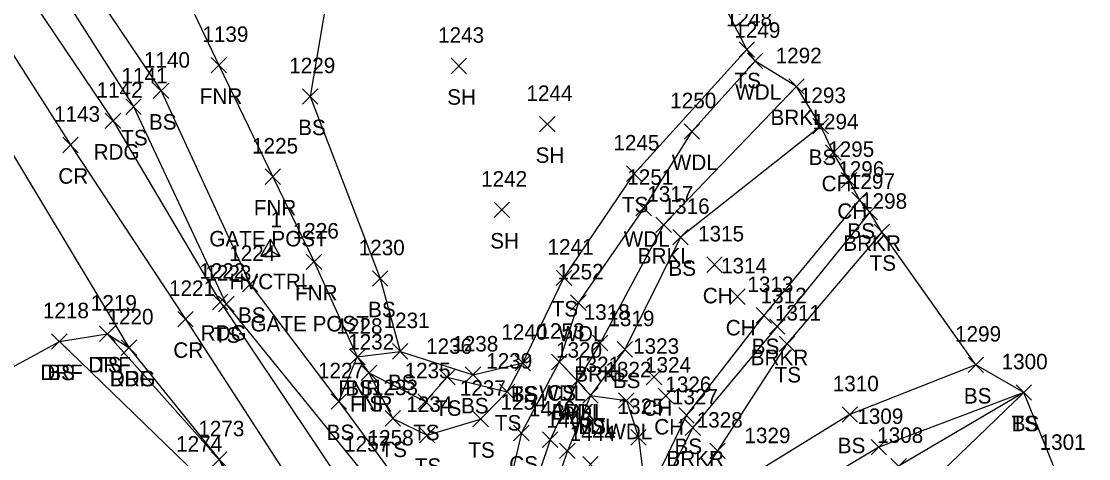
# Model space of a CAD drawing. Extents: x 1441651 to 1442140, y 243798 to 245625.
# Drawn here: x 1441999.2 to 1442137.1, y 245444.6 to 245501.1 of the extents above; entities that cross this region are included whole.
import ezdxf

# ---------------------------------------------------------------- set-up
doc = ezdxf.new("R2010")
doc.units = 0
for name, color, linetype in [('C_A', 7, 'Continuous'), ('C_I', 7, 'Continuous'), ('CPSM', 7, 'Continuous'), ('L_A', 7, 'Continuous'), ('L_C', 7, 'Continuous'), ('L_I', 7, 'Continuous'), ('L_TIC', 7, 'Continuous'), ('LAWA', 7, 'Continuous'), ('LAWE', 7, 'Continuous'), ('LELB', 7, 'Continuous'), ('LFNC', 7, 'Continuous'), ('LSOGP', 7, 'Continuous'), ('P_A', 7, 'Continuous'), ('P_I', 7, 'Continuous'), ('P_TIC', 7, 'Continuous'), ('PEU', 7, 'Continuous'), ('PRC', 7, 'Continuous'), ('R_A', 7, 'Continuous'), ('R_I', 7, 'Continuous'), ('R_TIC', 7, 'Continuous'), ('RDF', 7, 'Continuous')]:
    doc.layers.add(name, color=color, linetype=linetype)

msp = doc.modelspace()

# ---------------------------------------------------------------- linework, layer by layer
at = {"layer": 'CPSM'}
for p, q in [((1442030.12, 245470.79), (1442031.37, 245472.96)), ((1442032.62, 245470.79), (1442031.37, 245472.96)), ((1442031.37, 245471.51), (1442031.37, 245472.96)), ((1442030.12, 245470.79), (1442031.37, 245471.51)), ((1442031.37, 245471.51), (1442031.37, 245471.51)), ((1442031.37, 245471.51), (1442032.62, 245470.79)), ((1442030.12, 245470.79), (1442032.62, 245470.79))]:
    msp.add_line(p, q, dxfattribs=at)
at = {"layer": 'L_TIC'}
for points in [[(1442091.91, 245496.47), (1442093.91, 245498.47)], [(1442093.91, 245496.47), (1442091.91, 245498.47)], [(1442023.69, 245494.45), (1442025.69, 245496.45)], [(1442025.69, 245494.45), (1442023.69, 245496.45)], [(1442054.71, 245494.34), (1442056.71, 245496.34)], [(1442056.71, 245494.34), (1442054.71, 245496.34)], [(1442093, 245494.98), (1442095, 245496.98)], [(1442095, 245494.98), (1442093, 245496.98)], [(1442016.22, 245491.13), (1442018.22, 245493.13)], [(1442018.22, 245491.13), (1442016.22, 245493.13)], [(1442098.33, 245491.7), (1442100.33, 245493.7)], [(1442100.33, 245491.7), (1442098.33, 245493.7)], [(1442035.49, 245490.41), (1442037.49, 245492.41)], [(1442037.49, 245490.41), (1442035.49, 245492.41)], [(1442035.49, 245490.41), (1442037.49, 245492.41)], [(1442037.49, 245490.41), (1442035.49, 245492.41)], [(1442012.67, 245489.09), (1442014.67, 245491.09)], [(1442014.67, 245489.09), (1442012.67, 245491.09)], [(1442066.14, 245486.83), (1442068.14, 245488.83)], [(1442068.14, 245486.83), (1442066.14, 245488.83)], [(1442084.8, 245485.89), (1442086.8, 245487.89)], [(1442086.8, 245485.89), (1442084.8, 245487.89)], [(1442101.46, 245486.56), (1442103.46, 245488.56)], [(1442103.46, 245486.56), (1442101.46, 245488.56)], [(1442103.09, 245483.16), (1442105.09, 245485.16)], [(1442105.09, 245483.16), (1442103.09, 245485.16)], [(1442030.67, 245480.04), (1442032.67, 245482.04)], [(1442032.67, 245480.04), (1442030.67, 245482.04)], [(1442077.37, 245480.43), (1442079.37, 245482.43)], [(1442079.37, 245480.43), (1442077.37, 245482.43)], [(1442105.12, 245479.6), (1442107.12, 245481.6)], [(1442107.12, 245479.6), (1442105.12, 245481.6)], [(1442060.27, 245475.77), (1442062.27, 245477.77)], [(1442062.27, 245475.77), (1442060.27, 245477.77)], [(1442078.59, 245476), (1442080.59, 245478)], [(1442080.59, 245476), (1442078.59, 245478)], [(1442106.48, 245477.04), (1442108.48, 245479.04)], [(1442108.48, 245477.04), (1442106.48, 245479.04)], [(1442107.8, 245475.47), (1442109.8, 245477.47)], [(1442109.8, 245475.47), (1442107.8, 245477.47)], [(1442081.17, 245473.83), (1442083.17, 245475.83)], [(1442083.17, 245473.83), (1442081.17, 245475.83)], [(1442083.35, 245472.24), (1442085.35, 245474.24)], [(1442085.35, 245472.24), (1442083.35, 245474.24)], [(1442109.37, 245472.9), (1442111.37, 245474.9)], [(1442111.37, 245472.9), (1442109.37, 245474.9)], [(1442035.99, 245469.06), (1442037.99, 245471.06)], [(1442037.99, 245469.06), (1442035.99, 245471.06)], [(1442087.73, 245468.69), (1442089.73, 245470.69)], [(1442089.73, 245468.69), (1442087.73, 245470.69)], [(1442027.73, 245466.17), (1442029.73, 245468.17)], [(1442029.73, 245466.17), (1442027.73, 245468.17)], [(1442044.54, 245466.9), (1442046.54, 245468.9)], [(1442046.54, 245466.9), (1442044.54, 245468.9)], [(1442068.29, 245466.99), (1442070.29, 245468.99)], [(1442070.29, 245466.99), (1442068.29, 245468.99)], [(1442024.65, 245463.6), (1442026.65, 245465.6)], [(1442026.65, 245463.6), (1442024.65, 245465.6)], [(1442070.15, 245463.78), (1442072.15, 245465.78)], [(1442072.15, 245463.78), (1442070.15, 245465.78)], [(1442090.7, 245464.55), (1442092.7, 245466.55)], [(1442092.7, 245464.55), (1442090.7, 245466.55)], [(1442094.11, 245462.14), (1442096.11, 245464.14)], [(1442096.11, 245462.14), (1442094.11, 245464.14)], [(1442095.83, 245460.7), (1442097.83, 245462.7)], [(1442097.83, 245460.7), (1442095.83, 245462.7)], [(1442009.28, 245459.76), (1442011.28, 245461.76)], [(1442011.28, 245459.76), (1442009.28, 245461.76)], [(1442003.08, 245458.77), (1442005.08, 245460.77)], [(1442005.08, 245458.77), (1442003.08, 245460.77)], [(1442072.96, 245458.56), (1442074.96, 245460.56)], [(1442074.96, 245458.56), (1442072.96, 245460.56)], [(1442097.1, 245458.47), (1442099.1, 245460.47)], [(1442099.1, 245458.47), (1442097.1, 245460.47)], [(1442041.58, 245456.76), (1442043.58, 245458.76)], [(1442043.58, 245456.76), (1442041.58, 245458.76)], [(1442041.58, 245456.76), (1442043.58, 245458.76)], [(1442043.58, 245456.76), (1442041.58, 245458.76)], [(1442047.11, 245457.49), (1442049.11, 245459.49)], [(1442049.11, 245457.49), (1442047.11, 245459.49)], [(1442047.11, 245457.49), (1442049.11, 245459.49)], [(1442049.11, 245457.49), (1442047.11, 245459.49)], [(1442076.16, 245457.74), (1442078.16, 245459.74)], [(1442078.16, 245457.74), (1442076.16, 245459.74)], [(1442062.98, 245455.99), (1442064.98, 245457.99)], [(1442064.98, 245455.99), (1442062.98, 245457.99)], [(1442062.98, 245455.99), (1442064.98, 245457.99)], [(1442064.98, 245455.99), (1442062.98, 245457.99)], [(1442067.68, 245456.12), (1442069.68, 245458.12)], [(1442069.68, 245456.12), (1442067.68, 245458.12)], [(1442067.68, 245456.12), (1442069.68, 245458.12)], [(1442069.68, 245456.12), (1442067.68, 245458.12)], [(1442121.52, 245455.75), (1442123.52, 245457.75)], [(1442123.52, 245455.75), (1442121.52, 245457.75)], [(1442043.09, 245454.72), (1442045.09, 245456.72)], [(1442045.09, 245454.72), (1442043.09, 245456.72)], [(1442043.09, 245454.72), (1442045.09, 245456.72)], [(1442045.09, 245454.72), (1442043.09, 245456.72)], [(1442043.09, 245454.72), (1442045.09, 245456.72)], [(1442045.09, 245454.72), (1442043.09, 245456.72)], [(1442053.21, 245454.16), (1442055.21, 245456.16)], [(1442055.21, 245454.16), (1442053.21, 245456.16)], [(1442056.54, 245454.47), (1442058.54, 245456.47)], [(1442058.54, 245454.47), (1442056.54, 245456.47)], [(1442079.92, 245454.17), (1442081.92, 245456.17)], [(1442081.92, 245454.17), (1442079.92, 245456.17)], [(1442070.04, 245453.67), (1442072.04, 245455.67)], [(1442072.04, 245453.67), (1442070.04, 245455.67)], [(1442070.04, 245453.67), (1442072.04, 245455.67)], [(1442072.04, 245453.67), (1442070.04, 245455.67)], [(1442039.19, 245451.02), (1442041.19, 245453.02)], [(1442041.19, 245451.02), (1442039.19, 245453.02)], [(1442039.19, 245451.02), (1442041.19, 245453.02)], [(1442041.19, 245451.02), (1442039.19, 245453.02)], [(1442050.39, 245451.01), (1442052.39, 245453.01)], [(1442052.39, 245451.01), (1442050.39, 245453.01)], [(1442060.95, 245452.26), (1442062.95, 245454.26)], [(1442062.95, 245452.26), (1442060.95, 245454.26)], [(1442060.95, 245452.26), (1442062.95, 245454.26)], [(1442062.95, 245452.26), (1442060.95, 245454.26)], [(1442071.72, 245451.8), (1442073.72, 245453.8)], [(1442073.72, 245451.8), (1442071.72, 245453.8)], [(1442071.72, 245451.8), (1442073.72, 245453.8)], [(1442073.72, 245451.8), (1442071.72, 245453.8)], [(1442076.35, 245451.14), (1442078.35, 245453.14)], [(1442078.35, 245451.14), (1442076.35, 245453.14)], [(1442081.46, 245451.75), (1442083.46, 245453.75)], [(1442083.46, 245451.75), (1442081.46, 245453.75)], [(1442127.7, 245452.17), (1442129.7, 245454.17)], [(1442129.7, 245452.17), (1442127.7, 245454.17)], [(1442127.7, 245452.17), (1442129.7, 245454.17)], [(1442129.7, 245452.17), (1442127.7, 245454.17)], [(1442127.7, 245452.17), (1442129.7, 245454.17)], [(1442129.7, 245452.17), (1442127.7, 245454.17)], [(1442046.17, 245448.83), (1442048.17, 245450.83)], [(1442048.17, 245448.83), (1442046.17, 245450.83)], [(1442057.52, 245448.75), (1442059.52, 245450.75)], [(1442059.52, 245448.75), (1442057.52, 245450.75)], [(1442084.12, 245449.23), (1442086.12, 245451.23)], [(1442086.12, 245449.23), (1442084.12, 245451.23)], [(1442105.23, 245449.33), (1442107.23, 245451.33)], [(1442107.23, 245449.33), (1442105.23, 245451.33)], [(1442062.78, 245446.95), (1442064.78, 245448.95)], [(1442064.78, 245446.95), (1442062.78, 245448.95)], [(1442084.94, 245447.64), (1442086.94, 245449.64)], [(1442086.94, 245447.64), (1442084.94, 245449.64)], [(1442050.6, 245446.67), (1442052.6, 245448.67)], [(1442052.6, 245446.67), (1442050.6, 245448.67)], [(1442066.5, 245446.08), (1442068.5, 245448.08)], [(1442068.5, 245446.08), (1442066.5, 245448.08)], [(1442077.91, 245446.39), (1442079.91, 245448.39)], [(1442079.91, 245446.39), (1442077.91, 245448.39)], [(1442068.73, 245444.65), (1442070.73, 245446.65)], [(1442070.73, 245444.65), (1442068.73, 245446.65)], [(1442088.13, 245444.64), (1442090.13, 245446.64)], [(1442090.13, 245444.64), (1442088.13, 245446.64)], [(1442108.97, 245445.11), (1442110.97, 245447.11)], [(1442110.97, 245445.11), (1442108.97, 245447.11)], [(1442023.73, 245443.52), (1442025.73, 245445.52)], [(1442025.73, 245443.52), (1442023.73, 245445.52)], [(1442071.71, 245442.9), (1442073.71, 245444.9)], [(1442073.71, 245442.9), (1442071.71, 245444.9)], [(1442111.53, 245442.67), (1442113.53, 245444.67)], [(1442113.53, 245442.67), (1442111.53, 245444.67)]]:
    msp.add_lwpolyline(points, dxfattribs=at)
at = {"layer": 'LAWA'}
msp.add_lwpolyline([(1442094, 245495.98), (1442085.8, 245486.89), (1442079.59, 245477), (1442071.15, 245464.78), (1442068.68, 245457.12), (1442071.04, 245454.67), (1442072.72, 245452.8), (1442077.35, 245452.14), (1442078.91, 245447.39), (1442079.93, 245439.38), (1442079.45, 245435.79), (1442079.26, 245431.04), (1442079.31, 245426.05), (1442080.91, 245421.58), (1442082.68, 245419.01), (1442083.61, 245417.34), (1442086, 245415.06), (1442087.36, 245410.97), (1442093.76, 245403.64), (1442092.69, 245393.5), (1442088.17, 245379.01), (1442081.06, 245357.62), (1442070.18, 245342.03)], dxfattribs=at)
at = {"layer": 'LAWE'}
for points in [[(1442099.33, 245492.7), (1442082.17, 245474.83), (1442073.96, 245459.56), (1442071.04, 245454.67), (1442067.5, 245447.08), (1442064.77, 245439.02), (1442060.82, 245433.99), (1442057.71, 245424.57), (1442056.02, 245422.42), (1442050.95, 245416.77), (1442046.42, 245406.15), (1442038.47, 245397.39), (1442033, 245390.02), (1442022.03, 245379.96), (1442015.44, 245373.01), (1442011.82, 245364.95), (1441999.31, 245341.93), (1441993.28, 245326.59), (1441983.7, 245301.8)], [(1442108.8, 245476.47), (1442096.83, 245461.7), (1442085.94, 245448.64), (1442079.45, 245435.79), (1442078.13, 245432.44), (1442074.22, 245419.93), (1442069.91, 245412.33), (1442066.17, 245406.44), (1442060.08, 245400.81), (1442053.87, 245394.97), (1442048.8, 245389.02), (1442033.75, 245369.5), (1442027.29, 245353.92), (1442016.14, 245332.93), (1442008.36, 245317.18), (1442000.26, 245295.5)]]:
    msp.add_lwpolyline(points, dxfattribs=at)
at = {"layer": 'LELB'}
for points in [[(1441958.14, 245603.85), (1441973.05, 245572.7), (1441987.15, 245544.68), (1442001.28, 245515.81), (1442017.22, 245492.13), (1442028.73, 245467.17), (1442040.19, 245452.02), (1442046.6, 245443.33), (1442055.54, 245439.06), (1442059.34, 245437.76)], [(1441952, 245600.36), (1441967.38, 245569.64), (1441982.75, 245542), (1441998.18, 245514.4), (1442013.67, 245490.09), (1442025.65, 245464.6), (1442043.56, 245442.55), (1442056.06, 245427.98)], [(1442054.94, 245535.31), (1442039.85, 245511.24), (1442036.49, 245491.41)], [(1442044.09, 245455.72), (1442051.39, 245452.01), (1442054.21, 245455.16), (1442061.95, 245453.26), (1442063.98, 245456.99), (1442069.29, 245467.99), (1442078.37, 245481.43), (1442092.91, 245497.47)], [(1442036.49, 245491.41), (1442045.54, 245467.9), (1442048.11, 245458.49), (1442057.54, 245455.47), (1442063.98, 245456.99)], [(1442102.46, 245487.56), (1442084.35, 245473.24), (1442077.16, 245458.74), (1442072.72, 245452.8), (1442069.73, 245445.65), (1442066.87, 245437.14), (1442063.41, 245431.6), (1442060.35, 245422.41), (1442058.71, 245418.73), (1442054.41, 245414.05), (1442047.26, 245402.98), (1442041.76, 245394.88), (1442035.1, 245387.22), (1442025.14, 245377.83), (1442014.24, 245362.92), (1442001.68, 245340.27), (1441995.17, 245325.26), (1441985.52, 245301.17)], [(1442107.48, 245478.04), (1442095.11, 245463.14), (1442085.12, 245450.23), (1442079.93, 245439.38), (1442074.02, 245430.6), (1442072.19, 245422.42), (1442067.6, 245415.77), (1442063.53, 245410.87), (1442058.94, 245403.45), (1442051.47, 245396.66), (1442047.36, 245390.55), (1442031.62, 245371.64), (1442024.89, 245355.94), (1442013.33, 245334.79), (1442005.48, 245318.66), (1441997.83, 245296.61)], [(1442110.37, 245473.9), (1442098.1, 245459.47), (1442089.13, 245445.64), (1442079.26, 245431.04)], [(1442010.28, 245460.76), (1442024.73, 245444.52), (1442033.88, 245425.53)], [(1442004.08, 245459.77), (1442021.87, 245442.55), (1442025.23, 245431.01), (1442028.78, 245424.28), (1442039.93, 245412.91)], [(1442040.19, 245452.02), (1442042.58, 245457.76), (1442048.11, 245458.49)], [(1442068.68, 245457.12), (1442063.78, 245447.95), (1442061.76, 245439.31), (1442059.81, 245436.82), (1442059.01, 245434.53), (1442059.88, 245434.24)], [(1442044.09, 245455.72), (1442047.17, 245449.83), (1442051.6, 245447.67), (1442058.52, 245449.75), (1442061.95, 245453.26)], [(1442122.52, 245456.75), (1442106.23, 245450.33), (1442095.31, 245443.63), (1442083.42, 245430.81), (1442079.31, 245426.05)], [(1442128.7, 245453.17), (1442114.47, 245439.46), (1442106.29, 245436.04), (1442091.13, 245416.25), (1442087.36, 245410.97), (1442078.92, 245407.7), (1442072.37, 245401.79), (1442078.66, 245393.32), (1442088.17, 245379.01), (1442078.35, 245359.72), (1442066.47, 245343.93), (1442051.62, 245313.9)], [(1442128.7, 245453.17), (1442112.53, 245443.67), (1442104.21, 245438.02), (1442088.68, 245419.94), (1442086, 245415.06), (1442079.92, 245412.18)], [(1442128.7, 245453.17), (1442109.97, 245446.11), (1442099.05, 245439.57), (1442087, 245426.32)]]:
    msp.add_lwpolyline(points, dxfattribs=at)
at = {"layer": 'LFNC'}
msp.add_lwpolyline([(1441970.22, 245607.54), (1441978.86, 245588.2), (1441995.27, 245556.04), (1442014.76, 245516.33), (1442024.69, 245495.45), (1442031.67, 245481.04), (1442036.99, 245470.06), (1442042.58, 245457.76), (1442044.09, 245455.72)], dxfattribs=at)
at = {"layer": 'LSOGP'}
msp.add_lwpolyline([(1442101.45, 245340.82), (1442116.12, 245368.4), (1442121.58, 245390.94), (1442129.6, 245411.58), (1442137.09, 245433.29), (1442136.43, 245438.34), (1442132.95, 245442.77), (1442128.7, 245453.17), (1442122.52, 245456.75), (1442110.37, 245473.9), (1442108.8, 245476.47), (1442107.48, 245478.04), (1442106.12, 245480.6), (1442104.09, 245484.16), (1442102.46, 245487.56), (1442099.33, 245492.7), (1442094, 245495.98), (1442092.91, 245497.47), (1442087.1, 245508.94)], dxfattribs=at)
at = {"layer": 'P_TIC'}
for points in [[(1442010.02, 245487.25), (1442012.02, 245489.25)], [(1442012.02, 245487.25), (1442010.02, 245489.25)], [(1442004.51, 245484.14), (1442006.51, 245486.14)], [(1442006.51, 245484.14), (1442004.51, 245486.14)], [(1442023.85, 245463.87), (1442025.85, 245465.87)], [(1442025.85, 245463.87), (1442023.85, 245465.87)], [(1442019.38, 245461.65), (1442021.38, 245463.65)], [(1442021.38, 245461.65), (1442019.38, 245463.65)], [(1442012.08, 245457.97), (1442014.08, 245459.97)], [(1442014.08, 245457.97), (1442012.08, 245459.97)], [(1442023.73, 245443.52), (1442025.73, 245445.52)], [(1442025.73, 245443.52), (1442023.73, 245445.52)]]:
    msp.add_lwpolyline(points, dxfattribs=at)
at = {"layer": 'PEU'}
for points in [[(1441949.7, 245598.81), (1441965.58, 245568.64), (1441979.81, 245540.54), (1441994.5, 245512.77), (1442011.02, 245488.25), (1442024.85, 245464.87), (1442045.34, 245434.3), (1442053.64, 245424.38)], [(1441937.94, 245591.88), (1441953.89, 245562.72), (1441968.91, 245535.69), (1441984.8, 245506.98), (1441992.99, 245492.3), (1442013.08, 245458.97), (1442024.73, 245444.52), (1442043.13, 245414.63), (1442048.27, 245419.3), (1442053.64, 245424.38)]]:
    msp.add_lwpolyline(points, dxfattribs=at)
at = {"layer": 'PRC'}
msp.add_lwpolyline([(1441943.37, 245595.22), (1441959.06, 245565.31), (1441973.71, 245538.05), (1441989.92, 245509.63), (1442005.51, 245485.14), (1442020.38, 245462.65), (1442040.92, 245430.94), (1442048.27, 245419.3)], dxfattribs=at)
at = {"layer": 'R_TIC'}
for points in [[(1442009.28, 245459.76), (1442011.28, 245461.76)], [(1442011.28, 245459.76), (1442009.28, 245461.76)], [(1442003.08, 245458.77), (1442005.08, 245460.77)], [(1442005.08, 245458.77), (1442003.08, 245460.77)], [(1442012.08, 245457.97), (1442014.08, 245459.97)], [(1442014.08, 245457.97), (1442012.08, 245459.97)]]:
    msp.add_lwpolyline(points, dxfattribs=at)
at = {"layer": 'RDF'}
msp.add_lwpolyline([(1441992.99, 245492.3), (1441993.22, 245488.68), (1441992.69, 245484.34), (1441989.24, 245472.33), (1441979.84, 245465.31), (1441969.62, 245458.62), (1441982.23, 245444.74), (1441988.43, 245451.23), (1442004.08, 245459.77), (1442010.28, 245460.76), (1442013.08, 245458.97)], dxfattribs=at)

# ---------------------------------------------------------------- texts
at = {"layer": 'C_A'}
msp.add_text('HVCTRL', height=2, dxfattribs=at).set_placement((1442026.07, 245466.51))
at = {"layer": 'C_I'}
msp.add_text('1', height=2, dxfattribs=at).set_placement((1442031.37, 245474.51))
at = {"layer": 'L_A'}
for s, p in [('TS', (1442091.32, 245492.47)), ('WDL', (1442091.42, 245490.98)), ('FNR', (1442022.23, 245490.45)), ('SH', (1442054.2, 245490.34)), ('BS', (1442015.66, 245487.13)), ('BRKL', (1442095.98, 245487.7)), ('BS', (1442034.94, 245486.41)), ('BS', (1442034.94, 245486.41)), ('TS', (1442012.08, 245485.09)), ('SH', (1442065.62, 245482.83)), ('WDL', (1442083.22, 245481.89)), ('BS', (1442100.9, 245482.56)), ('CH', (1442102.58, 245479.16)), ('FNR', (1442029.21, 245476.04)), ('TS', (1442076.78, 245476.43)), ('CH', (1442104.61, 245475.6)), ('BS', (1442105.92, 245473.04)), ('SH', (1442059.76, 245471.77)), ('WDL', (1442077.01, 245472)), ('BRKR', (1442105.39, 245471.47)), ('BRKL', (1442078.82, 245469.83)), ('TS', (1442108.78, 245468.9)), ('BS', (1442082.79, 245468.24)), ('FNR', (1442034.53, 245465.06)), ('CH', (1442087.22, 245464.69)), ('BS', (1442027.17, 245462.17)), ('BS', (1442043.98, 245462.9)), ('TS', (1442067.7, 245462.99)), ('CH', (1442090.19, 245460.55)), ('TS', (1442024.06, 245459.6)), ('WDL', (1442068.57, 245459.78)), ('BS', (1442093.55, 245458.14)), ('BRKR', (1442093.42, 245456.7)), ('TS', (1442008.69, 245455.76)), ('BS', (1442002.52, 245454.77)), ('BRKL', (1442070.61, 245454.56)), ('BS', (1442075.6, 245453.74)), ('TS', (1442096.51, 245454.47)), ('FNR', (1442040.12, 245452.76)), ('BS', (1442041.02, 245452.76)), ('BS', (1442046.55, 245453.49)), ('BS', (1442046.55, 245453.49)), ('TS', (1442062.39, 245451.99)), ('BS', (1442062.42, 245451.99)), ('WDL', (1442066.1, 245452.12)), ('CS', (1442067.12, 245452.12)), ('BS', (1442120.96, 245451.75)), ('FNR', (1442041.63, 245450.72)), ('TS', (1442042.5, 245450.72)), ('TS', (1442042.5, 245450.72)), ('TS', (1442052.62, 245450.16)), ('BS', (1442055.98, 245450.47)), ('BRKL', (1442067.69, 245449.67)), ('WDL', (1442068.46, 245449.67)), ('CH', (1442079.41, 245450.17)), ('TS', (1442060.36, 245448.26)), ('TS', (1442060.36, 245448.26)), ('TS', (1442127.11, 245448.17)), ('TS', (1442127.11, 245448.17)), ('BS', (1442127.14, 245448.17)), ('BS', (1442038.63, 245447.02)), ('BS', (1442038.63, 245447.02)), ('TS', (1442049.8, 245447.01)), ('WDL', (1442070.13, 245447.8)), ('BS', (1442071.16, 245447.8)), ('WDL', (1442074.76, 245447.14)), ('CH', (1442080.95, 245447.75)), ('TS', (1442045.58, 245444.83)), ('TS', (1442056.93, 245444.75)), ('BS', (1442083.57, 245445.23)), ('BS', (1442104.67, 245445.33)), ('TS', (1442050.01, 245442.67)), ('CS', (1442062.22, 245442.95)), ('BRKR', (1442082.53, 245443.64))]:
    msp.add_text(s, height=2, dxfattribs=at).set_placement(p)
at = {"layer": 'L_C'}
for p in [(1442023.46, 245472.04), (1442028.78, 245461.06)]:
    msp.add_text('GATE POST', height=2, dxfattribs=at).set_placement(p)
at = {"layer": 'L_I'}
for s, p in [('1248', (1442090.22, 245500.47)), ('1139', (1442022.56, 245498.45)), ('1243', (1442053.02, 245498.34)), ('1249', (1442091.3, 245498.98)), ('1140', (1442015.01, 245495.13)), ('1292', (1442096.64, 245495.7)), ('1229', (1442033.79, 245494.41)), ('1229', (1442033.79, 245494.41)), ('1141', (1442012.11, 245493.09)), ('1244', (1442064.44, 245490.83)), ('1250', (1442083.02, 245489.89)), ('1293', (1442099.77, 245490.56)), ('1294', (1442101.4, 245487.16)), ('1225', (1442028.98, 245484.04)), ('1245', (1442075.67, 245484.43)), ('1295', (1442103.43, 245483.6)), ('1251', (1442077.47, 245480)), ('1296', (1442104.73, 245481.04)), ('1242', (1442058.58, 245479.77)), ('1297', (1442106.11, 245479.47)), ('1317', (1442080.05, 245477.83)), ('1316', (1442082.16, 245476.24)), ('1298', (1442107.68, 245476.9)), ('1226', (1442034.24, 245473.06)), ('1315', (1442086.61, 245472.69)), ('1230', (1442042.76, 245470.9)), ('1241', (1442067.16, 245470.99)), ('1224', (1442026.03, 245470.17)), ('1223', (1442022.95, 245467.6)), ('1252', (1442068.46, 245467.78)), ('1314', (1442089.58, 245468.55)), ('1313', (1442092.99, 245466.14)), ('1312', (1442094.7, 245464.7)), ('1219', (1442008.15, 245463.76)), ('1218', (1442001.96, 245462.77)), ('1318', (1442071.84, 245462.56)), ('1311', (1442096.55, 245462.47)), ('1228', (1442039.89, 245460.76)), ('1228', (1442039.89, 245460.76)), ('1231', (1442045.98, 245461.49)), ('1231', (1442045.98, 245461.49)), ('1319', (1442075.03, 245461.74)), ('1240', (1442061.2, 245459.99)), ('1240', (1442061.2, 245459.99)), ('1253', (1442065.99, 245460.12)), ('1253', (1442065.99, 245460.12)), ('1299', (1442119.82, 245459.75)), ('1232', (1442041.4, 245458.72)), ('1232', (1442041.4, 245458.72)), ('1232', (1442041.4, 245458.72)), ('1236', (1442051.47, 245458.16)), ('1238', (1442054.85, 245458.47)), ('1323', (1442078.22, 245458.17)), ('1320', (1442068.26, 245457.67)), ('1320', (1442068.26, 245457.67)), ('1239', (1442059.24, 245456.26)), ('1239', (1442059.24, 245456.26)), ('1321', (1442070.59, 245455.8)), ('1321', (1442070.59, 245455.8)), ('1322', (1442074.65, 245455.14)), ('1324', (1442079.76, 245455.75)), ('1300', (1442125.84, 245456.17)), ('1300', (1442125.84, 245456.17)), ('1300', (1442125.84, 245456.17)), ('1227', (1442037.5, 245455.02)), ('1227', (1442037.5, 245455.02)), ('1235', (1442048.69, 245455.01)), ('1233', (1442044.47, 245452.83)), ('1237', (1442055.83, 245452.75)), ('1326', (1442082.38, 245453.23)), ('1310', (1442104.02, 245453.33)), ('1254', (1442061.09, 245450.95)), ('1327', (1442083.24, 245451.64)), ('1234', (1442048.91, 245450.67)), ('1446', (1442064.75, 245450.08)), ('1325', (1442076.21, 245450.39)), ('1445', (1442067.04, 245448.65)), ('1328', (1442086.44, 245448.64)), ('1309', (1442107.19, 245449.11)), ('1273', (1442022.04, 245447.52)), ('1444', (1442070.02, 245446.9)), ('1274', (1442019.17, 245445.55)), ('1257', (1442040.87, 245445.55)), ('1258', (1442043.91, 245446.33)), ('1329', (1442092.61, 245446.63)), ('1308', (1442109.76, 245446.67)), ('1301', (1442130.75, 245445.77))]:
    msp.add_text(s, height=2, dxfattribs=at).set_placement(p)
at = {"layer": 'P_A'}
for s, p in [('RDG', (1442008.5, 245483.25)), ('CR', (1442003.95, 245480.14)), ('RDG', (1442022.34, 245459.87)), ('CR', (1442018.81, 245457.65)), ('RDG', (1442010.56, 245453.97))]:
    msp.add_text(s, height=2, dxfattribs=at).set_placement(p)
at = {"layer": 'P_I'}
for s, p in [('1142', (1442008.89, 245491.25)), ('1143', (1442003.39, 245488.14)), ('1222', (1442022.16, 245467.87)), ('1221', (1442018.25, 245465.65)), ('1220', (1442010.3, 245461.97)), ('1273', (1442022.04, 245447.52))]:
    msp.add_text(s, height=2, dxfattribs=at).set_placement(p)
at = {"layer": 'R_A'}
for p in [(1442007.82, 245455.76), (1442001.62, 245454.77), (1442010.61, 245453.97)]:
    msp.add_text('DRF', height=2, dxfattribs=at).set_placement(p)
at = {"layer": 'R_I'}
for s, p in [('1219', (1442008.15, 245463.76)), ('1218', (1442001.96, 245462.77)), ('1220', (1442010.3, 245461.97)), ('1257', (1442040.87, 245445.55))]:
    msp.add_text(s, height=2, dxfattribs=at).set_placement(p)

doc.saveas('drawing.dxf')
